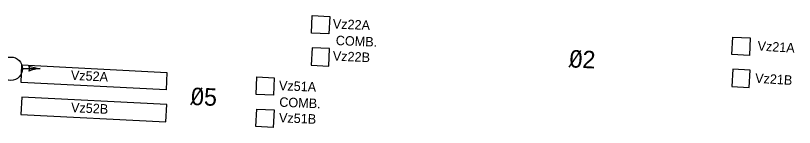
# Model space of a CAD drawing. Extents: x 647787 to 668496, y 640478 to 654412.
# Drawn here: x 648200.7 to 648468.8, y 648518.8 to 648557.2 of the extents above; entities that cross this region are included whole.
import ezdxf

# ---------------------------------------------------------------- set-up
doc = ezdxf.new("R2010")
doc.units = 0
for name, color, linetype in [('Default', 7, 'Continuous'), ('TEMP_SIGNAL_POLES_STAGE 1A', 7, 'Continuous'), ('TEMP_SIGNAL_POLES_STAGE 1B', 7, 'Continuous')]:
    doc.layers.add(name, color=color, linetype=linetype)

msp = doc.modelspace()

# ---------------------------------------------------------------- linework, layer by layer
at = {"layer": 'Default'}
for p, q in [((648391.33, 648539.53), (648395.3, 648545.24)), ((648261.04, 648526.63), (648264.96, 648532.37))]:
    msp.add_line(p, q, dxfattribs=at)
at = {"layer": 'TEMP_SIGNAL_POLES_STAGE 1A'}
msp.add_line((648203.04, 648539.02), (648209.1, 648539.06), dxfattribs=at)
msp.add_circle((648199.04, 648538.99), 4, dxfattribs=at)
for centre, radius, start, end in [((648203.84, 648539.02), 1.63, 328.53, 32.2246), ((648213.32, 648568.22), 29.47, 254.0409, 261.779), ((648213.71, 648509.95), 29.47, 98.9966, 106.7347)]:
    msp.add_arc(centre, radius, start, end, dxfattribs=at)
at = {"layer": 'TEMP_SIGNAL_POLES_STAGE 1B'}
for p, q in [((648302.52, 648551.22), (648302.83, 648557.21)), ((648302.83, 648557.21), (648308.82, 648556.91)), ((648308.82, 648556.91), (648308.51, 648550.91)), ((648308.51, 648550.91), (648302.52, 648551.22)), ((648447.33, 648543.86), (648447.64, 648549.86)), ((648447.64, 648549.86), (648453.63, 648549.54)), ((648453.63, 648549.54), (648453.33, 648543.56)), ((648302.78, 648546.2), (648302.48, 648540.21)), ((648308.77, 648545.89), (648302.78, 648546.2)), ((648308.47, 648539.9), (648308.77, 648545.89)), ((648453.33, 648543.56), (648447.33, 648543.86)), ((648202.56, 648534.27), (648202.86, 648540.26)), ((648302.48, 648540.21), (648308.47, 648539.9)), ((648447.59, 648538.84), (648447.29, 648532.85)), ((648453.59, 648538.53), (648447.59, 648538.84)), ((648453.28, 648532.53), (648453.59, 648538.53)), ((648252.8, 648537.72), (648252.49, 648531.73)), ((648283.45, 648530.16), (648283.76, 648536.15)), ((648289.75, 648535.85), (648289.45, 648529.85)), ((648447.29, 648532.85), (648453.28, 648532.53)), ((648202.82, 648529.25), (648202.51, 648523.25)), ((648252.75, 648526.71), (648202.82, 648529.25)), ((648252.45, 648520.72), (648252.75, 648526.71)), ((648283.41, 648519.15), (648283.71, 648525.14)), ((648283.71, 648525.14), (648289.71, 648524.83)), ((648202.51, 648523.25), (648252.45, 648520.72)), ((648289.71, 648524.83), (648289.4, 648518.84)), ((648289.4, 648518.84), (648283.41, 648519.15))]:
    msp.add_line(p, q, dxfattribs=at)
for points in [[(648202.86, 648540.26), (648252.8, 648537.72)], [(648283.76, 648536.15), (648289.75, 648535.85)], [(648252.49, 648531.73), (648202.56, 648534.27)], [(648289.45, 648529.85), (648283.45, 648530.16)]]:
    msp.add_lwpolyline(points, dxfattribs=at)

# ---------------------------------------------------------------- texts
at = {"layer": 'Default'}
for s, rotation, p in [('02', 357.3266, (648391.27, 648539.45)), ('05', 357.8528, (648260.98, 648526.54))]:
    msp.add_text(s, height=6, rotation=rotation, dxfattribs=at).set_placement(p)
at = {"layer": 'TEMP_SIGNAL_POLES_STAGE 1B'}
for s, rotation, p in [('Vz22A', 357.6447, (648309.85, 648552.79)), ('COMB.', 357.6447, (648310.87, 648547.1)), ('Vz21A', 356.5579, (648456.07, 648545.24)), ('Vz22B', 357.6447, (648309.85, 648541.77)), ('Vz52A', 357.3176, (648219.64, 648535.16)), ('Vz21B', 356.5579, (648455.24, 648534.17)), ('Vz51A', 357.6447, (648291.3, 648531.61)), ('COMB.', 357.6447, (648291.41, 648525.95)), ('Vz52B', 357.3176, (648219.69, 648524.1)), ('Vz51B', 357.6447, (648291.31, 648520.59))]:
    msp.add_text(s, height=3.25, rotation=rotation, dxfattribs=at).set_placement(p)

doc.saveas('drawing.dxf')
